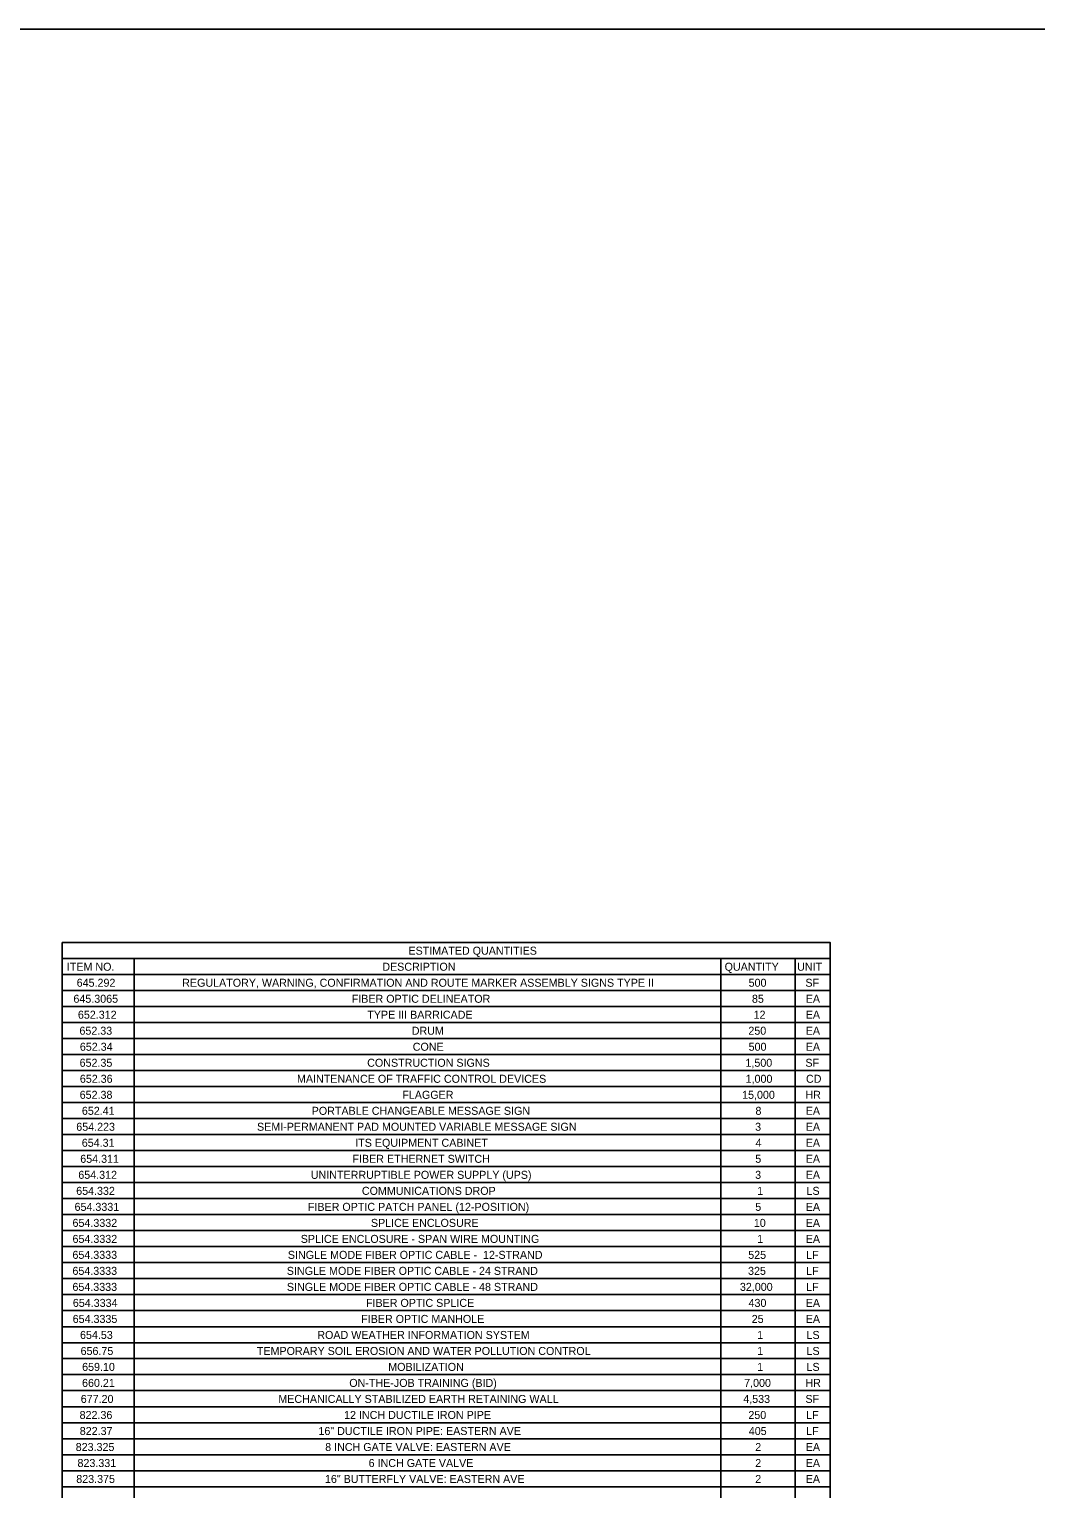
# Model space of a CAD drawing. Extents: x -18.7 to 5.6, y -2.7 to 5.1.
# Drawn here: x -5.226 to -3.989, y 3.303 to 5.098 of the extents above; entities that cross this region are included whole.
import ezdxf

# ---------------------------------------------------------------- set-up
doc = ezdxf.new("R2010")
doc.units = 0
for name, color, linetype in [('ANNOTATION', 7, 'Continuous'), ('BORDER', 7, 'Continuous'), ('Default', 7, 'Continuous')]:
    doc.layers.add(name, color=color, linetype=linetype)

msp = doc.modelspace()

# ---------------------------------------------------------------- linework, layer by layer
at = {"layer": 'BORDER'}
for p, q in [((-5.186, 3.9551), (-4.2418, 3.9551)), ((-5.0975, 3.9551), (-5.0975, 2.2424)), ((-4.3761, 3.9551), (-4.3761, 2.2424)), ((-4.2848, 3.9551), (-4.2848, 2.2424)), ((-5.186, 3.9354), (-4.2418, 3.9354)), ((-5.186, 3.9157), (-4.2418, 3.9157)), ((-5.186, 3.896), (-4.2418, 3.896)), ((-5.186, 3.8764), (-4.2418, 3.8764)), ((-5.186, 3.8567), (-4.2418, 3.8567)), ((-5.186, 3.837), (-4.2418, 3.837)), ((-5.186, 3.8173), (-4.2418, 3.8173)), ((-5.186, 3.7976), (-4.2418, 3.7976)), ((-5.186, 3.7779), (-4.2418, 3.7779)), ((-5.186, 3.7582), (-4.2418, 3.7582)), ((-5.186, 3.7386), (-4.2418, 3.7386)), ((-5.186, 3.7189), (-4.2418, 3.7189)), ((-5.186, 3.6992), (-4.2418, 3.6992)), ((-5.186, 3.6795), (-4.2418, 3.6795)), ((-5.186, 3.6598), (-4.2418, 3.6598)), ((-5.186, 3.6401), (-4.2418, 3.6401)), ((-5.186, 3.6204), (-4.2418, 3.6204)), ((-5.186, 3.6008), (-4.2418, 3.6008)), ((-5.186, 3.5811), (-4.2418, 3.5811)), ((-5.186, 3.5614), (-4.2418, 3.5614)), ((-5.186, 3.5417), (-4.2418, 3.5417)), ((-5.186, 3.522), (-4.2418, 3.522)), ((-5.186, 3.5023), (-4.2418, 3.5023)), ((-5.186, 3.4826), (-4.2418, 3.4826)), ((-5.186, 3.463), (-4.2418, 3.463)), ((-5.186, 3.4433), (-4.2418, 3.4433)), ((-5.186, 3.4236), (-4.2418, 3.4236)), ((-5.186, 3.4039), (-4.2418, 3.4039)), ((-5.186, 3.3842), (-4.2418, 3.3842)), ((-5.186, 3.3645), (-4.2418, 3.3645)), ((-5.186, 3.3448), (-4.2418, 3.3448)), ((-5.186, 3.3251), (-4.2418, 3.3251)), ((-5.186, 3.3055), (-4.2418, 3.3055))]:
    msp.add_line(p, q, dxfattribs=at)
msp.add_lwpolyline([(-5.186, 3.9748), (-4.2418, 3.9748), (-4.2418, 2.2424), (-5.186, 2.2424)], close=True, dxfattribs=at)
at = {"layer": 'Default'}
msp.add_lwpolyline([(-10.8151, 5.0978), (-2.7516, 5.0978), (-2.7516, 1.5028), (-10.8151, 1.5028)], close=True, dxfattribs=at)

# ---------------------------------------------------------------- texts
at = {"layer": 'ANNOTATION'}
for s, height, p in [('645.292', 0.00984, (-5.168, 3.9203)), ('REGULATORY, WARNING, CONFIRMATION AND ROUTE MARKER ASSEMBLY SIGNS TYPE II', 0.009843, (-5.0383, 3.9203)), ('500', 0.00984, (-4.342, 3.9203)), ('SF', 0.00984, (-4.2722, 3.9203)), ('645.3065', 0.00984, (-5.172, 3.9006)), ('FIBER OPTIC DELINEATOR', 0.009843, (-4.8299, 3.9006)), ('85', 0.00984, (-4.3379, 3.9006)), ('EA', 0.00984, (-4.2718, 3.9006)), ('652.312', 0.00984, (-5.1665, 3.881)), ('TYPE III BARRICADE', 0.009843, (-4.8108, 3.881)), ('12', 0.00984, (-4.3359, 3.881)), ('EA', 0.00984, (-4.2718, 3.881)), ('652.33', 0.00984, (-5.1646, 3.8613)), ('DRUM', 0.00984, (-4.7561, 3.8613)), ('250', 0.00984, (-4.3423, 3.8613)), ('EA', 0.00984, (-4.2718, 3.8613)), ('652.34', 0.00984, (-5.1641, 3.8416)), ('CONE', 0.00984, (-4.7549, 3.8416)), ('500', 0.00984, (-4.342, 3.8416)), ('EA', 0.00984, (-4.2718, 3.8416)), ('652.35', 0.00984, (-5.1644, 3.8219)), ('CONSTRUCTION SIGNS', 0.009843, (-4.8109, 3.8219)), ('1,500', 0.00984, (-4.3459, 3.8219)), ('SF', 0.00984, (-4.2722, 3.8219)), ('652.36', 0.00984, (-5.1641, 3.8022)), ('MAINTENANCE OF TRAFFIC CONTROL DEVICES', 0.009843, (-4.8972, 3.8022)), ('1,000', 0.00984, (-4.3457, 3.8022)), ('CD', 0.00984, (-4.2715, 3.8022)), ('652.38', 0.00984, (-5.1643, 3.7825)), ('FLAGGER', 0.00984, (-4.7677, 3.7825)), ('15,000', 0.00984, (-4.35, 3.7825)), ('HR', 0.00984, (-4.2722, 3.7825)), ('652.41', 0.00984, (-5.1616, 3.7628)), ('PORTABLE CHANGEABLE MESSAGE SIGN', 0.009843, (-4.8791, 3.7628)), ('8', 0.00984, (-4.3336, 3.7628)), ('EA', 0.00984, (-4.2718, 3.7628)), ('654.223', 0.00984, (-5.1685, 3.7432)), ('SEMI-PERMANENT PAD MOUNTED VARIABLE MESSAGE SIGN', 0.009843, (-4.9463, 3.7432)), ('3', 0.00984, (-4.334, 3.7432)), ('EA', 0.00984, (-4.2718, 3.7432)), ('654.31', 0.00984, (-5.1617, 3.7235)), ('ITS EQUIPMENT CABINET  ', 0.009843, (-4.8256, 3.7235)), ('4', 0.00984, (-4.3335, 3.7235)), ('EA', 0.00984, (-4.2718, 3.7235)), ('654.311', 0.00984, (-5.1636, 3.7038)), ('FIBER ETHERNET SWITCH ', 0.009843, (-4.829, 3.7038)), ('5', 0.00984, (-4.3338, 3.7038)), ('EA', 0.00984, (-4.2718, 3.7038)), ('654.312', 0.00984, (-5.166, 3.6841)), ('UNINTERRUPTIBLE POWER SUPPLY (UPS)', 0.009843, (-4.8802, 3.6841)), ('3', 0.00984, (-4.334, 3.6841)), ('EA', 0.00984, (-4.2718, 3.6841)), ('654.332', 0.00984, (-5.1686, 3.6644)), ('COMMUNICATIONS DROP', 0.009843, (-4.8174, 3.6644)), ('1', 0.00984, (-4.3315, 3.6644)), ('LS', 0.00984, (-4.2708, 3.6644)), ('654.3331', 0.00984, (-5.1706, 3.6447)), ('FIBER OPTIC PATCH PANEL (12-POSITION)', 0.009843, (-4.8838, 3.6447)), ('5', 0.00984, (-4.3338, 3.6447)), ('EA', 0.00984, (-4.2718, 3.6447)), ('654.3332', 0.00984, (-5.1731, 3.625)), ('SPLICE ENCLOSURE', 0.009843, (-4.8063, 3.625)), ('10', 0.00984, (-4.3356, 3.625)), ('EA', 0.00984, (-4.2718, 3.625)), ('654.3332', 0.00984, (-5.1731, 3.6053)), ('SPLICE ENCLOSURE - SPAN WIRE MOUNTING', 0.009843, (-4.8926, 3.6053)), ('1', 0.00984, (-4.3315, 3.6053)), ('EA', 0.00984, (-4.2718, 3.6053)), ('654.3333', 0.00984, (-5.1732, 3.5857)), ('SINGLE MODE FIBER OPTIC CABLE -  12-STRAND', 0.009843, (-4.9084, 3.5857)), ('525', 0.00984, (-4.3425, 3.5857)), ('LF', 0.00984, (-4.2712, 3.5857)), ('654.3333', 0.00984, (-5.1732, 3.566)), ('SINGLE MODE FIBER OPTIC CABLE - 24 STRAND', 0.009843, (-4.9097, 3.566)), ('325', 0.00984, (-4.3427, 3.566)), ('LF', 0.00984, (-4.2712, 3.566)), ('654.3333', 0.00984, (-5.1732, 3.5463)), ('SINGLE MODE FIBER OPTIC CABLE - 48 STRAND', 0.009843, (-4.9096, 3.5463)), ('32,000', 0.00984, (-4.3527, 3.5463)), ('LF', 0.00984, (-4.2712, 3.5463)), ('654.3334', 0.00984, (-5.1727, 3.5266)), ('FIBER OPTIC SPLICE ', 0.009843, (-4.8124, 3.5266)), ('430', 0.00984, (-4.3421, 3.5266)), ('EA', 0.00984, (-4.2718, 3.5266)), ('654.3335', 0.00984, (-5.1729, 3.5069)), ('FIBER OPTIC MANHOLE ', 0.009843, (-4.8183, 3.5069)), ('25', 0.00984, (-4.3382, 3.5069)), ('EA', 0.00984, (-4.2718, 3.5069)), ('654.53', 0.00984, (-5.1639, 3.4872)), ('ROAD WEATHER INFORMATION SYSTEM', 0.009843, (-4.8722, 3.4872)), ('1', 0.00984, (-4.3315, 3.4872)), ('LS', 0.00984, (-4.2708, 3.4872)), ('656.75', 0.00984, (-5.1632, 3.4675)), ('TEMPORARY SOIL EROSION AND WATER POLLUTION CONTROL', 0.009843, (-4.9465, 3.4675)), ('1', 0.00984, (-4.3315, 3.4675)), ('LS', 0.00984, (-4.2708, 3.4675)), ('659.10', 0.00984, (-5.1613, 3.4479)), ('MOBILIZATION', 0.009843, (-4.785, 3.4479)), ('1', 0.00984, (-4.3315, 3.4479)), ('LS', 0.00984, (-4.2708, 3.4479)), ('660.21', 0.00984, (-5.1614, 3.4282)), ('ON-THE-JOB TRAINING (BID)', 0.009843, (-4.8329, 3.4282)), ('7,000', 0.00984, (-4.3475, 3.4282)), ('HR', 0.00984, (-4.2722, 3.4282)), ('677.20', 0.00984, (-5.163, 3.4085)), ('MECHANICALLY STABILIZED EARTH RETAINING WALL', 0.009843, (-4.9201, 3.4085)), ('4,533', 0.00984, (-4.3486, 3.4085)), ('SF', 0.00984, (-4.2722, 3.4085)), ('822.36', 0.00984, (-5.1644, 3.3888)), ('12 INCH DUCTILE IRON PIPE', 0.009843, (-4.8393, 3.3888)), ('250', 0.00984, (-4.3423, 3.3888)), ('LF', 0.00984, (-4.2712, 3.3888)), ('822.37', 0.00984, (-5.1642, 3.3691)), ('16" DUCTILE IRON PIPE: EASTERN AVE', 0.009843, (-4.8708, 3.3691)), ('405', 0.00984, (-4.3418, 3.3691)), ('LF', 0.00984, (-4.2712, 3.3691)), ('823.325', 0.00984, (-5.1692, 3.3494)), ('8 INCH GATE VALVE: EASTERN AVE', 0.009843, (-4.8625, 3.3494)), ('2', 0.00984, (-4.3339, 3.3494)), ('EA', 0.00984, (-4.2718, 3.3494)), ('823.331', 0.00984, (-5.167, 3.3297)), ('6 INCH GATE VALVE', 0.009843, (-4.8091, 3.3297)), ('2', 0.00984, (-4.3339, 3.3297)), ('EA', 0.00984, (-4.2718, 3.3297)), ('823.375', 0.00984, (-5.1685, 3.3101)), ('16" BUTTERFLY VALVE: EASTERN AVE', 0.009843, (-4.8628, 3.3101)), ('2', 0.00984, (-4.3339, 3.3101)), ('EA', 0.00984, (-4.2718, 3.3101))]:
    msp.add_text(s, height=height, dxfattribs=at).set_placement(p)
at = {"layer": 'BORDER'}
for s, height, p in [('ESTIMATED QUANTITIES', 0.009843, (-4.7602, 3.9597)), ('ITEM NO.', 0.00984, (-5.1801, 3.94)), ('DESCRIPTION', 0.009843, (-4.7923, 3.94)), ('QUANTITY', 0.00984, (-4.3715, 3.94)), ('UNIT', 0.00984, (-4.2824, 3.94))]:
    msp.add_text(s, height=height, dxfattribs=at).set_placement(p)

doc.saveas('drawing.dxf')
